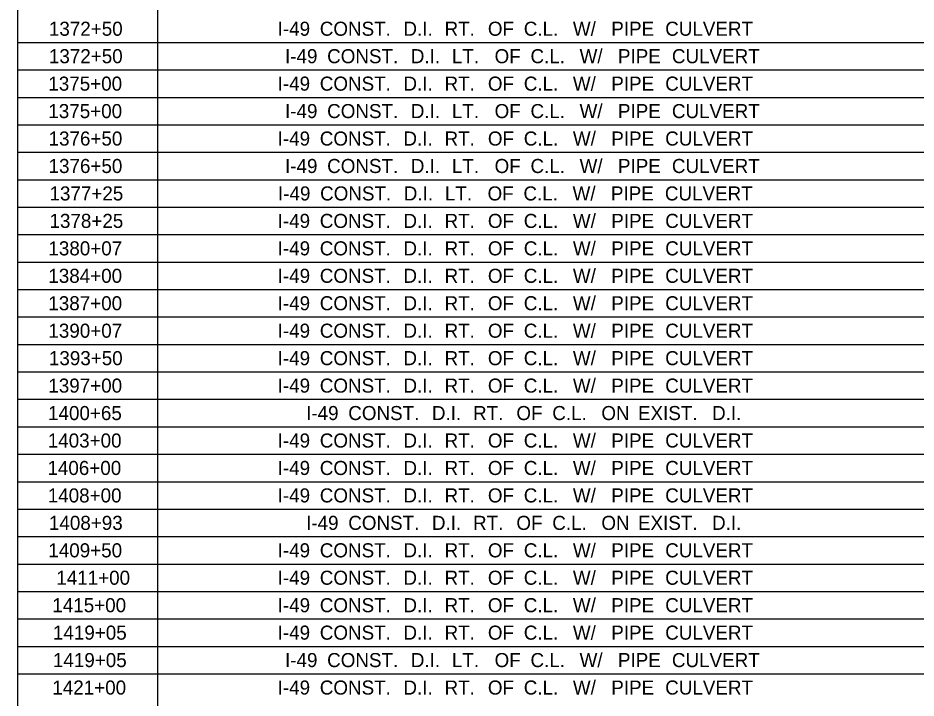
# Model space of a CAD drawing. Extents: x 1226564 to 1228153, y 151309 to 152340.
# Drawn here: x 1226563.6 to 1226835.5, y 151543.2 to 151749.1 of the extents above; entities that cross this region are included whole.
import ezdxf

# ---------------------------------------------------------------- set-up
doc = ezdxf.new("R2010")
doc.units = 0
doc.layers.add('R_Dimension', color=7, linetype='Continuous')

msp = doc.modelspace()

# ---------------------------------------------------------------- linework, layer by layer
at = {"layer": 'R_Dimension'}
for p, q in [((1226563.55, 151354.44), (1226563.55, 152160.49)), ((1226605.93, 151369.4), (1226605.93, 152160.49)), ((1226563.55, 151741.68), (1228152.75, 151741.68)), ((1226563.55, 151733.37), (1228152.75, 151733.37)), ((1226563.55, 151725.06), (1228152.75, 151725.06)), ((1226563.55, 151716.75), (1228152.75, 151716.75)), ((1226563.55, 151708.44), (1228152.75, 151708.44)), ((1226563.55, 151700.13), (1228152.75, 151700.13)), ((1226563.55, 151691.82), (1228152.75, 151691.82)), ((1226563.55, 151683.51), (1228152.75, 151683.51)), ((1226563.55, 151675.2), (1228152.75, 151675.2)), ((1226563.55, 151666.89), (1228152.75, 151666.89)), ((1226563.55, 151658.58), (1228152.75, 151658.58)), ((1226563.55, 151650.27), (1228152.75, 151650.27)), ((1226563.55, 151641.96), (1228152.75, 151641.96)), ((1226563.55, 151633.65), (1228152.75, 151633.65)), ((1226563.55, 151625.34), (1228152.75, 151625.34)), ((1226563.55, 151617.03), (1228152.75, 151617.03)), ((1226563.55, 151608.72), (1228152.75, 151608.72)), ((1226563.55, 151600.41), (1228152.75, 151600.41)), ((1226563.55, 151592.1), (1228152.75, 151592.1)), ((1226563.55, 151583.79), (1228152.75, 151583.79)), ((1226563.55, 151575.48), (1228152.75, 151575.48)), ((1226563.55, 151567.17), (1228152.75, 151567.17)), ((1226563.55, 151558.86), (1228152.75, 151558.86)), ((1226563.55, 151550.55), (1228152.75, 151550.55))]:
    msp.add_line(p, q, dxfattribs=at)

# ---------------------------------------------------------------- texts
for s, p in [('1372+50', (1226572.92, 151743.7)), ('I-49', (1226642.19, 151743.7)), (' CONST.', (1226653.36, 151743.7)), (' D.I.', (1226678.69, 151743.7)), (' RT.', (1226691.14, 151743.7)), (' OF', (1226704.26, 151743.7)), (' C.L.', (1226715.13, 151743.7)), (' W/', (1226730, 151743.7)), (' PIPE', (1226741.61, 151743.7)), (' CULVERT', (1226757.95, 151743.7)), ('1372+50', (1226572.92, 151735.39)), ('I-49', (1226644.42, 151735.39)), (' CONST.', (1226655.59, 151735.39)), (' D.I.', (1226680.93, 151735.39)), (' LT.', (1226693.37, 151735.39)), (' OF', (1226706.29, 151735.39)), (' C.L.', (1226717.16, 151735.39)), (' W/', (1226732.03, 151735.39)), (' PIPE', (1226743.64, 151735.39)), (' CULVERT', (1226759.98, 151735.39)), ('1375+00', (1226572.75, 151727.08)), ('I-49', (1226642.19, 151727.08)), (' CONST.', (1226653.36, 151727.08)), (' OF', (1226704.26, 151727.08)), (' C.L.', (1226715.13, 151727.08)), (' W/', (1226730, 151727.08)), (' CULVERT', (1226757.95, 151727.08)), (' D.I.', (1226678.69, 151727.08)), (' RT.', (1226691.14, 151727.08)), (' PIPE', (1226741.61, 151727.08)), (' W/', (1226732.03, 151718.77)), ('1375+00', (1226572.75, 151718.77)), ('I-49', (1226644.42, 151718.77)), (' CONST.', (1226655.59, 151718.77)), (' D.I.', (1226680.93, 151718.77)), (' LT.', (1226693.37, 151718.77)), (' OF', (1226706.29, 151718.77)), (' C.L.', (1226717.16, 151718.77)), (' PIPE', (1226743.64, 151718.77)), (' CULVERT', (1226759.98, 151718.77)), ('1376+50', (1226572.82, 151710.46)), ('I-49', (1226642.19, 151710.46)), (' CONST.', (1226653.36, 151710.46)), (' D.I.', (1226678.69, 151710.46)), (' RT.', (1226691.14, 151710.46)), (' OF', (1226704.26, 151710.46)), (' C.L.', (1226715.13, 151710.46)), (' W/', (1226730, 151710.46)), (' PIPE', (1226741.61, 151710.46)), (' CULVERT', (1226757.95, 151710.46)), ('1376+50', (1226572.82, 151702.15)), ('I-49', (1226644.42, 151702.15)), (' CONST.', (1226655.59, 151702.15)), (' D.I.', (1226680.93, 151702.15)), (' LT.', (1226693.37, 151702.15)), (' OF', (1226706.29, 151702.15)), (' C.L.', (1226717.16, 151702.15)), (' W/', (1226732.03, 151702.15)), (' PIPE', (1226743.64, 151702.15)), (' CULVERT', (1226759.98, 151702.15)), ('1377+25', (1226573.1, 151693.84)), ('I-49', (1226642.29, 151693.84)), (' CONST.', (1226653.46, 151693.84)), (' D.I.', (1226678.79, 151693.84)), (' LT.', (1226691.24, 151693.84)), (' OF', (1226704.16, 151693.84)), (' C.L.', (1226715.03, 151693.84)), (' W/', (1226729.9, 151693.84)), (' PIPE', (1226741.51, 151693.84)), (' CULVERT', (1226757.85, 151693.84)), ('1378+25', (1226573.1, 151685.53)), ('I-49', (1226642.19, 151685.53)), (' CONST.', (1226653.36, 151685.53)), (' D.I.', (1226678.69, 151685.53)), (' RT.', (1226691.14, 151685.53)), (' OF', (1226704.26, 151685.53)), (' C.L.', (1226715.13, 151685.53)), (' W/', (1226730, 151685.53)), (' PIPE', (1226741.61, 151685.53)), (' CULVERT', (1226757.95, 151685.53)), ('1380+07', (1226572.77, 151677.22)), ('I-49', (1226642.19, 151677.22)), (' CONST.', (1226653.36, 151677.22)), (' D.I.', (1226678.69, 151677.22)), (' RT.', (1226691.14, 151677.22)), (' OF', (1226704.26, 151677.22)), (' C.L.', (1226715.13, 151677.22)), (' W/', (1226730, 151677.22)), (' PIPE', (1226741.61, 151677.22)), (' CULVERT', (1226757.95, 151677.22)), ('1384+00', (1226572.75, 151668.91)), ('I-49', (1226642.19, 151668.91)), (' CONST.', (1226653.36, 151668.91)), (' D.I.', (1226678.69, 151668.91)), (' RT.', (1226691.14, 151668.91)), (' OF', (1226704.26, 151668.91)), (' C.L.', (1226715.13, 151668.91)), (' W/', (1226730, 151668.91)), (' PIPE', (1226741.61, 151668.91)), (' CULVERT', (1226757.95, 151668.91)), ('1387+00', (1226572.75, 151660.6)), ('I-49', (1226642.19, 151660.6)), (' CONST.', (1226653.36, 151660.6)), (' D.I.', (1226678.69, 151660.6)), (' RT.', (1226691.14, 151660.6)), (' OF', (1226704.26, 151660.6)), (' C.L.', (1226715.13, 151660.6)), (' W/', (1226730, 151660.6)), (' PIPE', (1226741.61, 151660.6)), (' CULVERT', (1226757.95, 151660.6)), ('1390+07', (1226572.77, 151652.29)), ('I-49', (1226642.19, 151652.29)), (' CONST.', (1226653.36, 151652.29)), (' D.I.', (1226678.69, 151652.29)), (' RT.', (1226691.14, 151652.29)), (' OF', (1226704.26, 151652.29)), (' C.L.', (1226715.13, 151652.29)), (' W/', (1226730, 151652.29)), (' PIPE', (1226741.61, 151652.29)), (' CULVERT', (1226757.95, 151652.29)), ('1393+50', (1226572.92, 151643.98)), ('I-49', (1226642.19, 151643.98)), (' CONST.', (1226653.36, 151643.98)), (' D.I.', (1226678.69, 151643.98)), (' RT.', (1226691.14, 151643.98)), (' OF', (1226704.26, 151643.98)), (' C.L.', (1226715.13, 151643.98)), (' W/', (1226730, 151643.98)), (' PIPE', (1226741.61, 151643.98)), (' CULVERT', (1226757.95, 151643.98)), ('1397+00', (1226572.75, 151635.67)), ('I-49', (1226642.19, 151635.67)), (' CONST.', (1226653.36, 151635.67)), (' D.I.', (1226678.69, 151635.67)), (' RT.', (1226691.14, 151635.67)), (' OF', (1226704.26, 151635.67)), (' C.L.', (1226715.13, 151635.67)), (' W/', (1226730, 151635.67)), (' PIPE', (1226741.61, 151635.67)), (' CULVERT', (1226757.95, 151635.67)), ('1400+65', (1226572.66, 151627.36)), ('I-49', (1226650.81, 151627.36)), (' CONST.', (1226661.98, 151627.36)), (' D.I.', (1226687.32, 151627.36)), (' RT.', (1226699.77, 151627.36)), (' OF', (1226712.89, 151627.36)), (' C.L.', (1226723.76, 151627.36)), (' ON', (1226738.62, 151627.36)), (' EXIST.', (1226749.7, 151627.36)), (' D.I.', (1226772.14, 151627.36)), ('1403+00', (1226572.58, 151619.05)), ('I-49', (1226642.19, 151619.05)), (' CONST.', (1226653.36, 151619.05)), (' D.I.', (1226678.69, 151619.05)), (' RT.', (1226691.14, 151619.05)), (' OF', (1226704.26, 151619.05)), (' C.L.', (1226715.13, 151619.05)), (' W/', (1226730, 151619.05)), (' PIPE', (1226741.61, 151619.05)), (' CULVERT', (1226757.95, 151619.05)), ('1406+00', (1226572.48, 151610.74)), ('I-49', (1226642.19, 151610.74)), (' CONST.', (1226653.36, 151610.74)), (' D.I.', (1226678.69, 151610.74)), (' RT.', (1226691.14, 151610.74)), (' OF', (1226704.26, 151610.74)), (' C.L.', (1226715.13, 151610.74)), (' W/', (1226730, 151610.74)), (' PIPE', (1226741.61, 151610.74)), (' CULVERT', (1226757.95, 151610.74)), ('1408+00', (1226572.58, 151602.43)), ('I-49', (1226642.19, 151602.43)), (' CONST.', (1226653.36, 151602.43)), (' D.I.', (1226678.69, 151602.43)), (' RT.', (1226691.14, 151602.43)), (' OF', (1226704.26, 151602.43)), (' C.L.', (1226715.13, 151602.43)), (' W/', (1226730, 151602.43)), (' PIPE', (1226741.61, 151602.43)), (' CULVERT', (1226757.95, 151602.43)), ('1408+93', (1226572.93, 151594.12)), ('I-49', (1226650.81, 151594.12)), (' CONST.', (1226661.98, 151594.12)), (' D.I.', (1226687.32, 151594.12)), (' RT.', (1226699.77, 151594.12)), (' OF', (1226712.89, 151594.12)), (' C.L.', (1226723.76, 151594.12)), (' ON', (1226738.62, 151594.12)), (' EXIST.', (1226749.7, 151594.12)), (' D.I.', (1226772.14, 151594.12)), ('1409+50', (1226572.75, 151585.81)), ('I-49', (1226642.19, 151585.81)), (' CONST.', (1226653.36, 151585.81)), (' D.I.', (1226678.69, 151585.81)), (' RT.', (1226691.14, 151585.81)), (' OF', (1226704.26, 151585.81)), (' C.L.', (1226715.13, 151585.81)), (' W/', (1226730, 151585.81)), (' PIPE', (1226741.61, 151585.81)), (' CULVERT', (1226757.95, 151585.81)), ('1411+00', (1226575.16, 151577.51)), ('I-49', (1226642.19, 151577.51)), (' CONST.', (1226653.36, 151577.51)), (' OF', (1226704.26, 151577.51)), (' C.L.', (1226715.13, 151577.51)), (' W/', (1226730, 151577.51)), (' CULVERT', (1226757.95, 151577.51)), (' D.I.', (1226678.69, 151577.51)), (' RT.', (1226691.14, 151577.51)), (' PIPE', (1226741.61, 151577.51)), (' W/', (1226730, 151569.2)), ('1415+00', (1226573.96, 151569.2)), ('I-49', (1226642.19, 151569.2)), (' CONST.', (1226653.36, 151569.2)), (' D.I.', (1226678.69, 151569.2)), (' RT.', (1226691.14, 151569.2)), (' OF', (1226704.26, 151569.2)), (' C.L.', (1226715.13, 151569.2)), (' PIPE', (1226741.61, 151569.2)), (' CULVERT', (1226757.95, 151569.2)), ('1419+05', (1226574.14, 151560.89)), ('I-49', (1226642.19, 151560.89)), (' CONST.', (1226653.36, 151560.89)), (' D.I.', (1226678.69, 151560.89)), (' RT.', (1226691.14, 151560.89)), (' OF', (1226704.26, 151560.89)), (' C.L.', (1226715.13, 151560.89)), (' W/', (1226730, 151560.89)), (' PIPE', (1226741.61, 151560.89)), (' CULVERT', (1226757.95, 151560.89)), ('1419+05', (1226574.14, 151552.58)), ('I-49', (1226644.42, 151552.58)), (' CONST.', (1226655.59, 151552.58)), (' D.I.', (1226680.93, 151552.58)), (' LT.', (1226693.37, 151552.58)), (' OF', (1226706.29, 151552.58)), (' C.L.', (1226717.16, 151552.58)), (' W/', (1226732.03, 151552.58)), (' PIPE', (1226743.64, 151552.58)), (' CULVERT', (1226759.98, 151552.58)), ('1421+00', (1226573.96, 151544.27)), ('I-49', (1226642.19, 151544.27)), (' CONST.', (1226653.36, 151544.27)), (' D.I.', (1226678.69, 151544.27)), (' RT.', (1226691.14, 151544.27)), (' OF', (1226704.26, 151544.27)), (' C.L.', (1226715.13, 151544.27)), (' W/', (1226730, 151544.27)), (' PIPE', (1226741.61, 151544.27)), (' CULVERT', (1226757.95, 151544.27))]:
    msp.add_text(s, height=4.261, dxfattribs=at).set_placement(p)

doc.saveas('drawing.dxf')
